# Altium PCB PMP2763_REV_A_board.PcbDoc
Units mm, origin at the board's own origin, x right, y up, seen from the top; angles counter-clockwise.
Board outline 41.91 x 33.66 mm, 2 copper layers (Top Layer, Top, Bottom Layer, Bottom); 43 components, 16 nets, 82 pads, 29 vias.
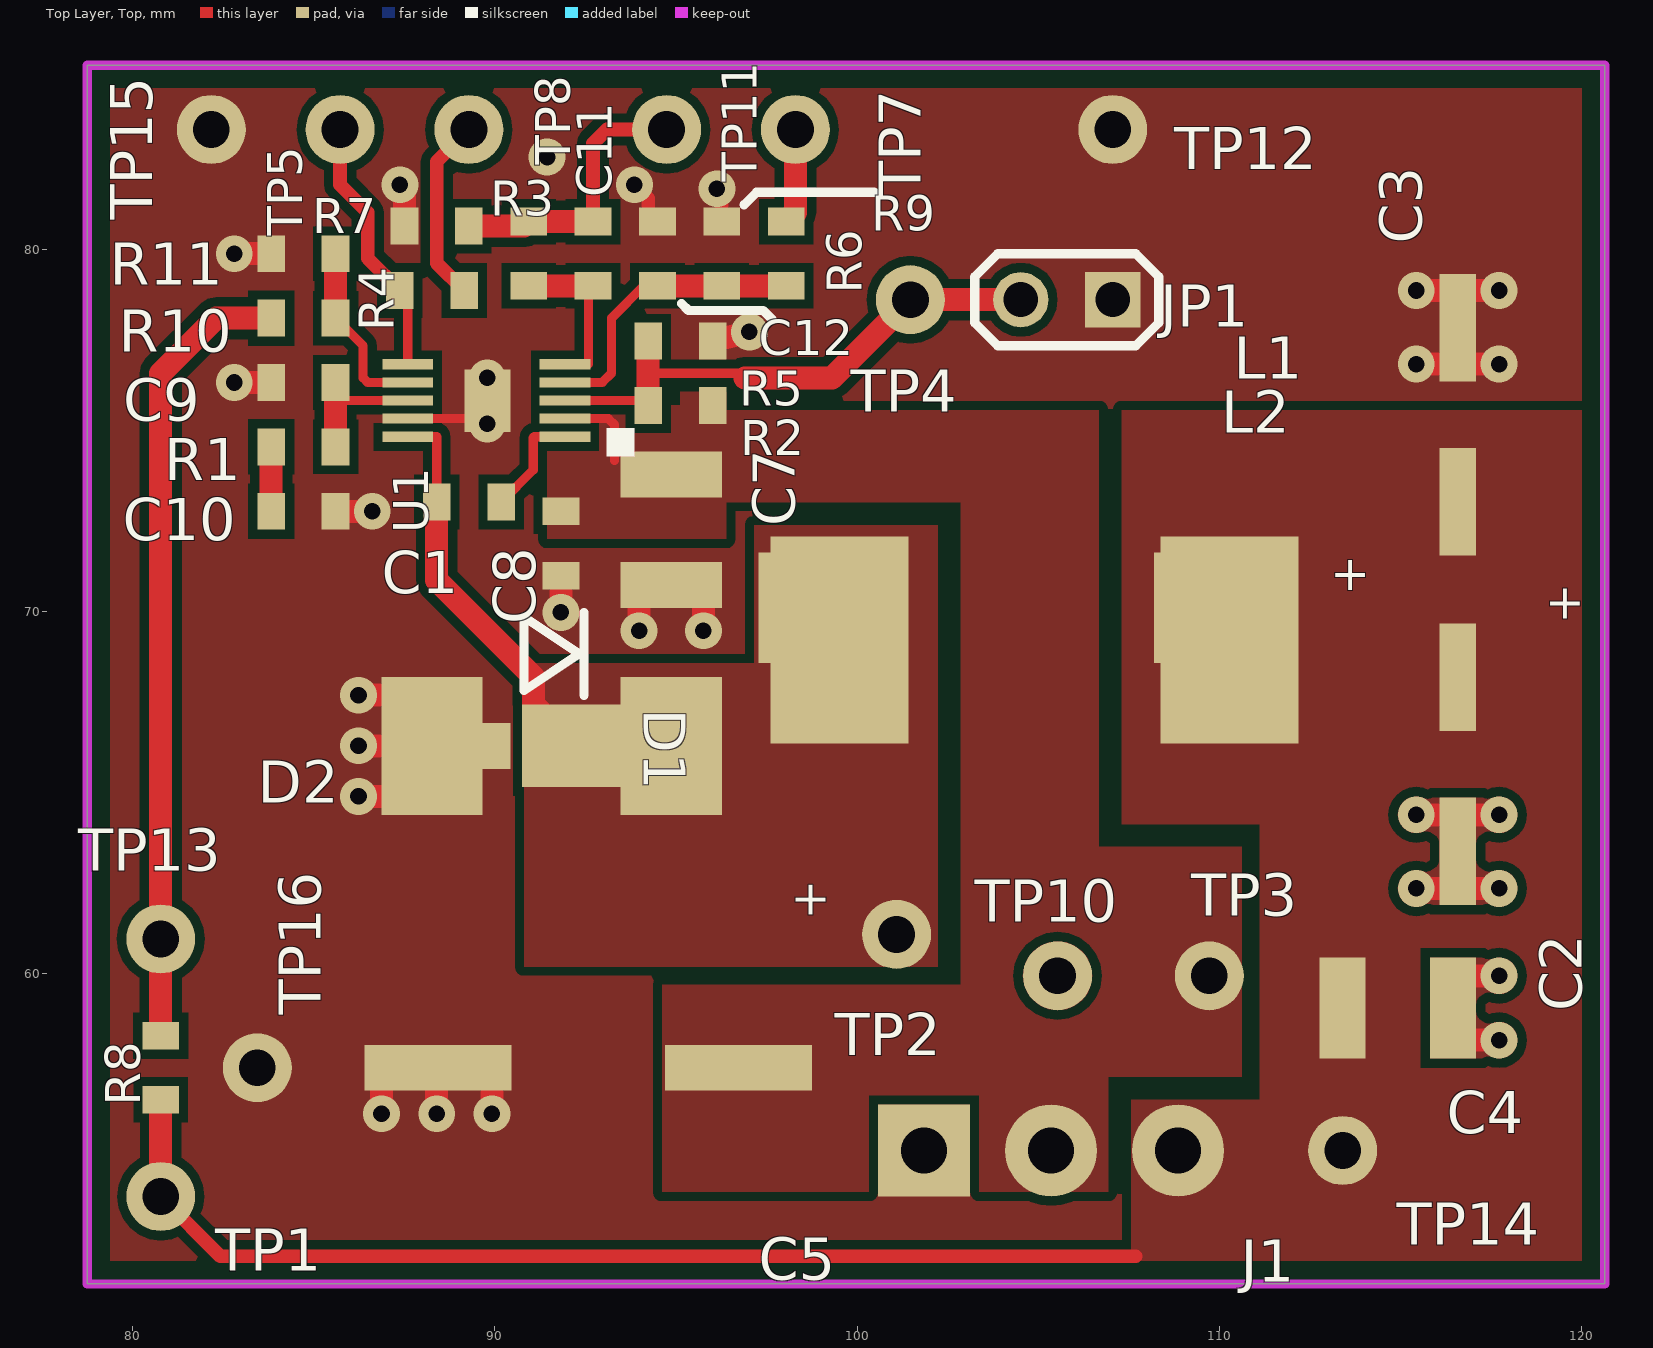
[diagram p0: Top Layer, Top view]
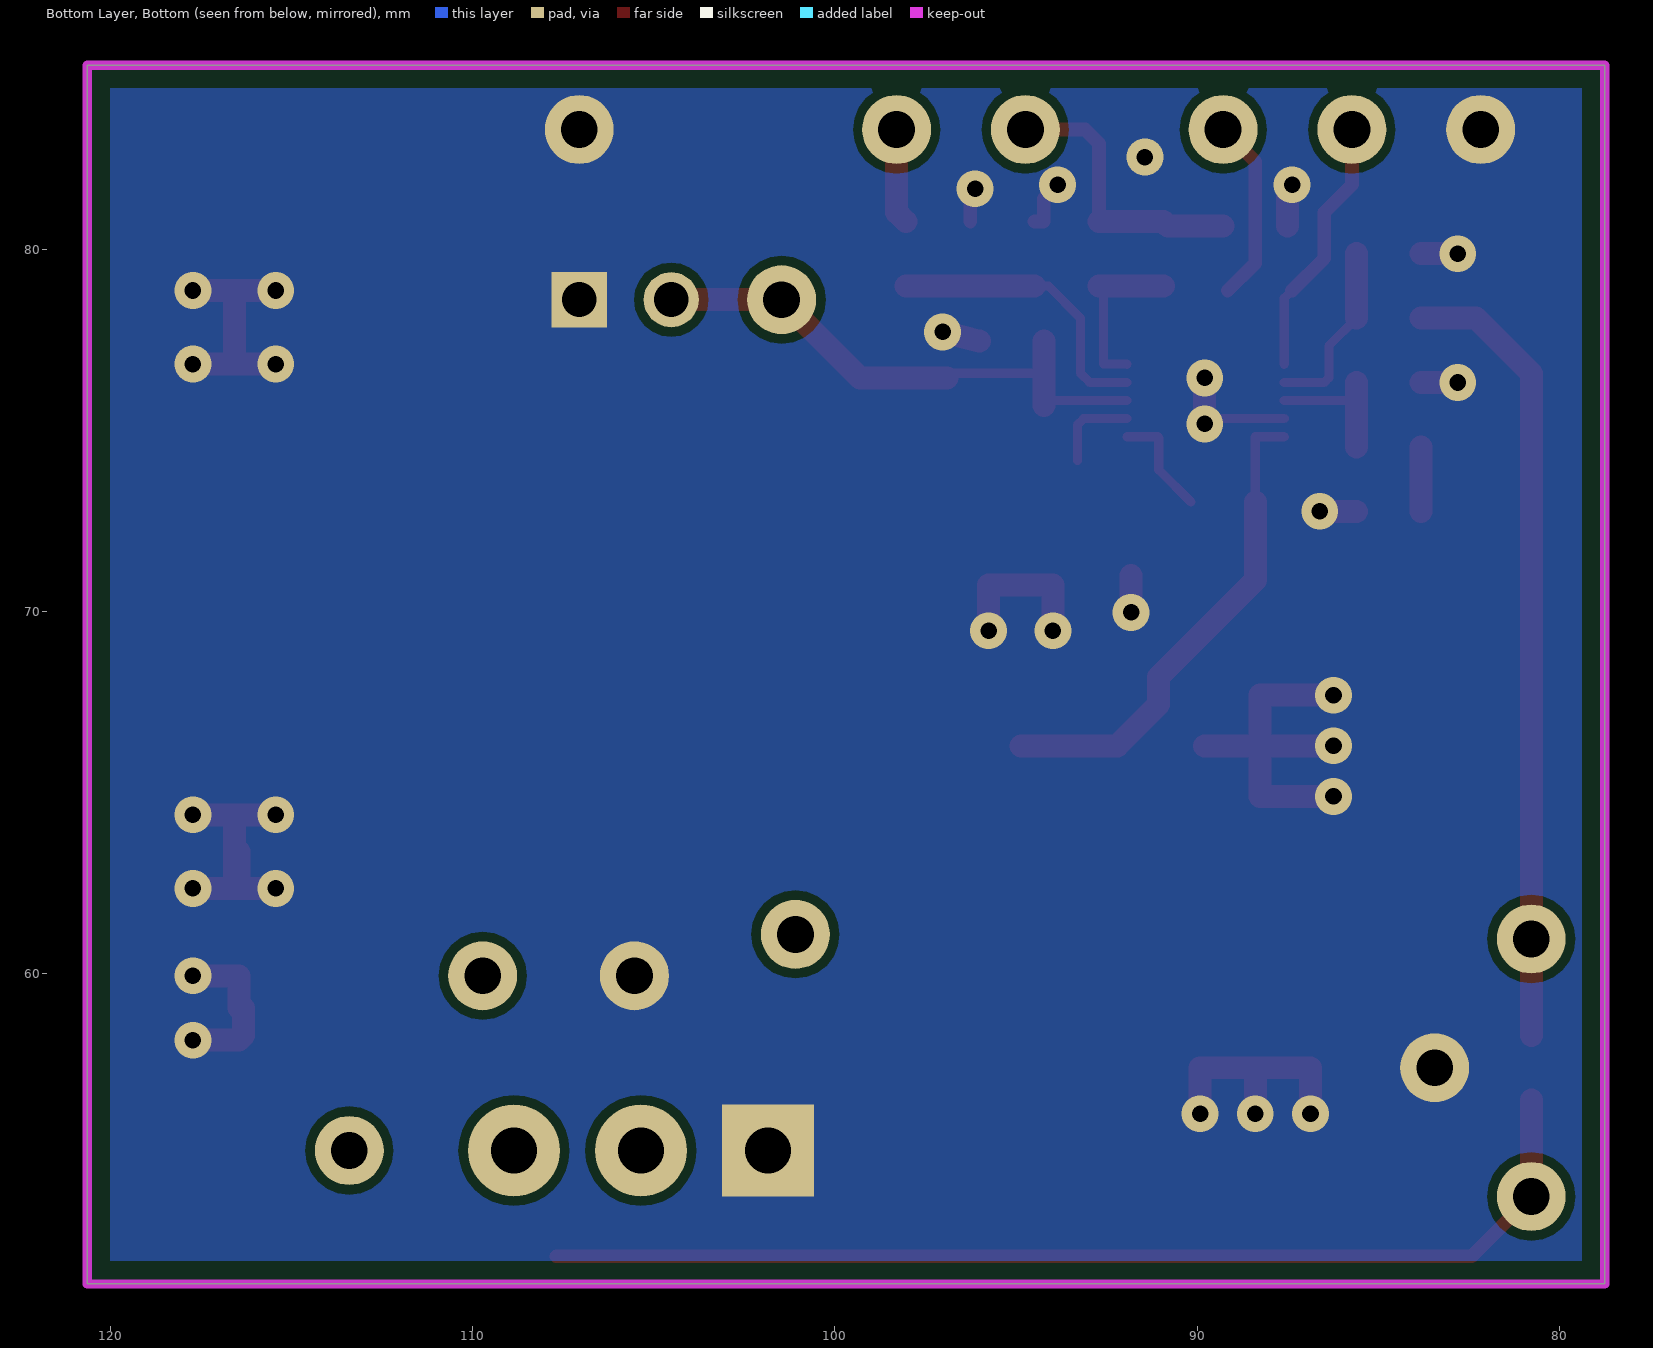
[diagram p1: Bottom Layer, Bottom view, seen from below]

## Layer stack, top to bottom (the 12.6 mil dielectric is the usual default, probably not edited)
Top Solder, Top Mask: solder mask 0.0102, Solder Resist, Dk 3.5
Top Layer, Top: signal copper 0.0356
Dielectric 1: dielectric 0.32, FR-4, Dk 4.8
Bottom Layer, Bottom: signal copper 0.0356
Bottom Solder, Bot Mask: solder mask 0.0102, Solder Resist, Dk 3.5

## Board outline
78.74,51.435 78.74,85.09 120.65,85.09 120.65,51.435

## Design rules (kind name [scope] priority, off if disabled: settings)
Clearance [All] p1: gap=0.254 ignorepadtopadclearanceinfootprint=FALSE except(0: Arc-Hole Track-Hole SMDPad-Hole THPad-Hole Via-Hole Fill-Hole Poly-Hole Region-Hole Text-Hole; 0.218: THPad-THPad; 0.231: Arc-THPad Track-THPad; 0.244: Arc-Arc Arc-Track Track-Track)
ComponentClearance [All] p1 off: gap=0.254 collisioncheckmode=3 verticalgap=0.254 showdistances=FALSE
HoleSize [All] p1: absolutevalues=TRUE maxlimit=2.54 minlimit=0.3 maxpercent=80.000 minpercent=20.000
PlaneClearance [All] p1: clearance=0.254
PolygonConnect PolygonConnect_10 [IsPolygon And InNet('GND') And OnLayer('Bottom Layer, Bottom') vs IsVia] p1: connectstyle=Direct reliefconductorwidth=0.381 reliefentries=4 polygonreliefangle="90 Angle" airgapwidth=0.254
PolygonConnect PolygonConnect_9 [IsPolygon And InNet('GND') And OnLayer('Bottom Layer, Bottom') vs IsPad] p2: connectstyle=Direct reliefconductorwidth=0.381 reliefentries=4 polygonreliefangle="90 Angle" airgapwidth=0.254
PolygonConnect PolygonConnect_8 [IsPolygon And InNet('GND') And OnLayer('Top Layer, Top') vs IsVia] p3: connectstyle=Direct reliefconductorwidth=0.381 reliefentries=4 polygonreliefangle="90 Angle" airgapwidth=0.254
PolygonConnect PolygonConnect_7 [IsPolygon And InNet('GND') And OnLayer('Top Layer, Top') vs IsPad] p4: connectstyle=Direct reliefconductorwidth=0.381 reliefentries=4 polygonreliefangle="90 Angle" airgapwidth=0.254
PolygonConnect PolygonConnect_6 [IsPolygon And InNet('PH') And OnLayer('Top Layer, Top') vs IsVia] p5: connectstyle=Direct reliefconductorwidth=0.381 reliefentries=4 polygonreliefangle="90 Angle" airgapwidth=0.254
PolygonConnect PolygonConnect_5 [IsPolygon And InNet('PH') And OnLayer('Top Layer, Top') vs IsPad] p6: connectstyle=Direct reliefconductorwidth=0.381 reliefentries=4 polygonreliefangle="90 Angle" airgapwidth=0.254
PolygonConnect PolygonConnect_4 [IsPolygon And InNet('VIN') And OnLayer('Top Layer, Top') vs IsVia] p7: connectstyle=Direct reliefconductorwidth=0.381 reliefentries=4 polygonreliefangle="90 Angle" airgapwidth=0.254
PolygonConnect PolygonConnect_3 [IsPolygon And InNet('VIN') And OnLayer('Top Layer, Top') vs IsPad] p8: connectstyle=Direct reliefconductorwidth=0.381 reliefentries=4 polygonreliefangle="90 Angle" airgapwidth=0.254
PolygonConnect PolygonConnect_2 [IsPolygon And InNet('VOUT') And OnLayer('Top Layer, Top') vs IsVia] p9: connectstyle=Direct reliefconductorwidth=0.381 reliefentries=4 polygonreliefangle="90 Angle" airgapwidth=0.254
PolygonConnect PolygonConnect_1 [IsPolygon And InNet('VOUT') And OnLayer('Top Layer, Top') vs IsPad] p10: connectstyle=Direct reliefconductorwidth=0.381 reliefentries=4 polygonreliefangle="90 Angle" airgapwidth=0.254
PolygonConnect [All] p11: connectstyle=Relief reliefconductorwidth=0.254 reliefentries=4 polygonreliefangle="90 Angle" airgapwidth=0.254
RoutingVias [All] p1: holewidth=0.711 width=1.27 viastyle="Through Hole" minholewidth=0.3 minwidth=0.7 maxholewidth=1 maxwidth=2
SolderMaskExpansion [All] p1: expansion=0.102 istentingtop=FALSE
Width [All] p1: maxlimit=2 minlimit=0.2 preferedwidth=0.8 toplayer_prefwidth=0.5 minimp=50.000000 maximp=50.000000 favimp=50.000000
27 further rules are at their usual default settings.

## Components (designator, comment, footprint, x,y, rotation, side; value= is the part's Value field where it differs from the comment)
C1 "Open" C603 89.281,73.025 r0 top
C2 "220uF" CAP_ALUM_FK-D 116.586,65.786 r0 top
C3 "Open" CAP_ALUM_FK-D 116.586,75.438 r180 top
C4 "10uF" C1210 114.935,59.055 r180 top
C5 "220uF" CAP_ALUM_FK-G 92.583,57.404 r270 top
C7 "Open" C1210 94.869,72.263 r90 top
C8 "0.1uF" C603 91.821,71.882 r90 top (schematic designator C9)
C9 "Open" C603 84.709,76.327 r0 top
C10 "Open" C603 84.709,72.771 r180 top
C11 "Open" C603 92.71,79.883 r270 top
C12 "Open" C603 94.488,79.883 r270 top
D1 "Open" D_457-04 92.329,66.294 r270 top
D2 "MBRS340" MOT_SMC_CASE 91.567,66.294 r180 top
J1 "ED555/3DS" TB_3X3.5MM 101.854,55.118 r0 top
JP1 "PTC36SAAN" HDR100_1X2 107.061,78.613 r180 top
L1 "Open" IND_DO3316P 104.14,70.104 r180 top
L2 "15 uH" IND_DR127 104.902,69.215 r90 top
R1 "open" R603 84.709,74.549 r180 top
R2 "open" R603 95.123,75.692 r0 top
R3 "open" R603 90.932,79.883 r270 top
R4 "open" R603 88.265,78.867 r180 top (schematic designator R5)
R5 "open" R603 95.123,77.47 r180 top
R6 "open" R603 98.044,79.883 r90 top
R7 "open" R603 88.392,80.645 r0 top
R8 "open" R603 80.772,57.404 r270 top
R9 "open" R603 96.266,79.883 r270 top
R10 "open" R603 84.709,78.105 r180 top
R11 "open" R603 84.709,79.883 r0 top
TP1 "5000" TH-40 80.772,53.848 r0 top
TP2 "5000" TH-40 101.092,61.087 r0 top
TP3 "5000" TH-40 109.728,59.944 r0 top
TP4 "5001" TH-40 101.473,78.613 r0 top
TP5 "5001" TH-40 85.725,83.312 r0 top
TP7 "5001" TH-40 98.298,83.312 r0 top
TP8 "5001" TH-40 89.281,83.312 r0 top
TP10 "5001" TH-40 105.537,59.944 r0 top
TP11 "5001" TH-40 94.742,83.312 r0 top
TP12 "5001" TH-40 107.061,83.312 r0 top
TP13 "5000" TH-40 80.772,60.96 r0 top
TP14 "5000" TH-40 113.411,55.118 r0 top
TP15 "5001" TH-40 82.169,83.312 r0 top
TP16 "5001" TH-40 83.439,57.404 r0 top
U1 "TPS54160DGQ" DGQ_10PWP 89.789,75.819 r180 top

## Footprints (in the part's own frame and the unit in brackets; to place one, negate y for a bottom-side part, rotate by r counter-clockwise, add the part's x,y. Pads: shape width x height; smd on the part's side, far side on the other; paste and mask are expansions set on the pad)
C603 [mil]
  rect 30x40 smd: 1(-35,0) 2(35,0)
C1210 [mil]
  rect 50x110 smd: 1(-60,0) 2(60,0)
CAP_ALUM_FK-D [mil]
  rect 40x117 smd: 1(0,94.5) 2(0,-94.5)
CAP_ALUM_FK-G [mil]
  rect 50x160 smd: 1(0,163.3) 2(0,-163.7)
D_457-04 [mil]
  rect 90x115 smd: 1(0,-5)
  rect 50x50 smd: 2(0,-100)
DGQ_10PWP [mil]
  rect 55x11 smd: 1(-84.5,39) 2(-84.5,19.3) 3(-84.5,-0.4) 4(-84.5,-20.1) 5(-84.5,-39.8) 6(86.5,-39.8) 7(86.5,-20.1) 8(86.5,-0.4) 9(86.5,19.3) 10(86.5,39)
  rect 50x68 smd: 11(0,0)
  silkscreen extent -160,30 -130,60
HDR100_1X2 [mil]
  rect 60x60 hole 38: 1(0,0)
  round 60 hole 38: 2(100,0)
  silkscreen extent -50,-50 150,50
IND_DO3316P [mil]
  rect 120x120 smd: 1(210,0) 2(-220,0)
IND_DR127 [mil]
  rect 225x150 smd: 1(0,212) 2(0,-212)
MOT_SMC_CASE [mil]
  rect 110x150 smd: 1(-130,0) 2(130,0)
  silkscreen extent -35,-145 30,-55
R603 [mil]
  rect 30x40 smd: 1(-35,0) 2(35,0)
TB_3X3.5MM [mil]
  rect 100x100 hole 50: 1(0,0)
  round 100 hole 50: 2(138,0) 3(276,0)
TH-40 [mil]
  round 75 hole 40: 1(0,0)

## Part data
C1 C12: library part GRM188R71E104KA01D, "CAP, CERM, 0.1 µF, 25 V, +/- 10%, X7R, 0603"
C2 C3 C4 C5 C7: library part GRM31CR72A225KA73L, "CAP, CERM, 2.2 µF, 100 V,+/- 10%, X7R, 1206"
C8: library part GRM1885C1H470JA01D, "CAP, CERM, 47 pF, 50 V,+/- 5%, C0G/NP0, 0603"
C9 C11: "Capacitor, Ceramic, vvV, [temp],  [tol]"
C10: library part GRM188R71E472KA01D, "CAP, CERM, 4700 pF, 25 V,+/- 10%, X7R, 0603"
D1: "Diode, Schottky, 1A, 40V"
D2: library part PMEG6020ER,115, "Diode, Schottky, 60 V, 2 A, SOD-123W"
J1: "Terminal Block, 6A, 3.5mm Pitch, 3-Pos, TH"
JP1: "Header, 2-pin,  100mil spacing, (36-pin strip)"
L1: "Inductor, SMT, yyA, zzmilliohm"
L2: library part CMP-0085398-2, "Inductor, Shielded, Composite, 33 µH, 3.6 A, 0.105 ohm, AEC-Q200 Grade 1, SMD"
R1: library part CRCW0603100KFKEA, "RES, 100 k, 1%, 0.1 W, 0603"
R2: library part CRCW0603130KFKEA, "RES, 130 k, 1%, 0.1 W, 0603"
R3: library part CRCW0603412KFKEA, "RES, 412 k, 1%, 0.1 W, 0603"
R4: library part CRCW060349K9FKEA, "RES, 49.9 k, 1%, 0.1 W, 0603"
R5 R6 R7 R9: "Resistor, Chip, 1/16W, 1%"
R8: library part CRCW060349R9FKEA, "RES, 49.9, 1%, 0.1 W, 0603"
R10: library part CRCW0603182KFKEA, "RES, 182 k, 1%, 0.1 W, 0603"
R11: library part CRCW06033K32FKEA, "RES, 3.32 k, 1%, 0.1 W, 0603"
TP1 TP3: "Test Point, Miniature, Red, TH"
TP2 TP4: library part 5002, "Test Point, Miniature, White, TH"
TP5 TP7 TP8 TP10 TP11 TP15: "Test Point,  Black, Thru Hole Color Keyed"
TP12: library part 5117, "Test Point, Miniature, Blue, TH"
TP13: library part 5004, "Test Point, Miniature, Yellow, TH"
TP14: library part 5001, "Test Point, Miniature, Black, TH"
TP16: "Test Point, Miniature, Black, TH"
U1: library part TPS54040ADGQ, "1.5 A, 60 V Step Down DC/DC Converter with Eco-mode, DGQ0010D"

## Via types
v1: diameter 1.016, hole 0.457, Top Layer, Top to Bottom Layer, Bottom, 29 vias

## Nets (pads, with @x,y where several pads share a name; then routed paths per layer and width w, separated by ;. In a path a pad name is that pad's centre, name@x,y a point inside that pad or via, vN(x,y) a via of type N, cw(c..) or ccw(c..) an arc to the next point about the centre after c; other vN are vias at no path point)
EN: JP1.2 R2.1 R5.2 TP4.1 U1.3 | length 16.3
  Top Layer, Top w0.254: U1.3 94.097,75.829 R2.1 ; R5.2 94.234,76.581 96.901,76.581 96.901,76.454
  Top Layer, Top w0.635: R2.1 94.234,76.581 R5.2 ; 96.901,76.454 99.314,76.454 TP4.1 JP1.2
GND: C2.2 C3.2 C4.1 C5.2 C7.1 C8.1 C9.1 C10.1 C12.1 D1.2 D2.2 J1.1 JP1.1 R5.1 R7.1 R9.1 R11.1 TP10.1 TP12.1 TP15.1 TP16.1 U1.9 U1.11 | length 54.9
  Top Layer, Top w0.254: U1.9 87.594,75.331 89.789,75.331 v1(89.789,75.184)
  Top Layer, Top w0.381: v1(93.853,81.788) 94.234,81.407 94.234,80.772 C12.1 ; v1(96.131,81.679) 96.266,81.661 R9.1
  Top Layer, Top w0.635: v1(82.804,76.327) C9.1 ; v1(82.804,79.883) R11.1 ; C10.1 v1(86.614,72.771) ; v1(86.233,64.897) 88.265,64.897 D2.2 ; v1(86.233,66.294) D2.2 ; v1(86.233,67.691) 88.265,67.691 D2.2 ; v1(86.868,56.134) 86.868,57.404 C5.2@88.392,57.404 ; v1(87.376,81.788) 87.503,81.661 R7.1 ; v1(88.392,56.134) C5.2@88.392,57.404 ; D1.2 D2.2 ; v1(89.789,75.184) 89.789,75.331 U1.11 v1(89.789,76.454) ; v1(89.916,56.134) 89.916,57.404 C5.2 C5.2@88.392,57.404 ; v1(91.821,69.977) C8.1 ; v1(93.98,69.469) 93.98,70.739 C7.1 95.758,70.739 v1(95.758,69.469) ; R5.1 v1(97.028,77.724) ; v1(115.443,62.357) C2.2@116.586,62.357 ; v1(115.443,64.389) C2.2@116.586,64.389 ; v1(115.443,76.835) C3.2@116.586,76.835 ; v1(115.443,78.867) C3.2@116.586,78.867 ; v1(117.729,58.166) 116.459,58.166 116.332,58.293 116.332,59.055 C4.1 116.459,59.944 v1(117.729,59.944) ; v1(117.729,62.357) C2.2@116.586,62.357 ; v1(117.729,64.389) C2.2@116.586,64.389 ; v1(117.729,76.835) C3.2@116.586,76.835 ; v1(117.729,78.867) C3.2@116.586,78.867 ; C2.2@116.586,62.357 C2.2 ; C2.2@116.586,62.357 116.459,62.484 116.459,63.373 C2.2 ; C2.2 C2.2@116.586,64.389 ; C2.2 C2.2@116.586,64.389 ; C3.2@116.586,76.835 C3.2 ; C3.2@116.586,76.835 C3.2 ; C3.2 C3.2@116.586,78.867
  other v1: 91.44,82.55
NET00006: C1.2 U1.1 | length 3
  Top Layer, Top w0.254: C1.2 91.059,73.914 91.059,74.803 91.084,74.828 U1.1
NET00007: R4.2 TP5.1 U1.6 | length 7.3
  Top Layer, Top w0.254: R4.2 87.592,78.651 U1.6
  Top Layer, Top w0.381: TP5.1 85.725,81.788 86.487,81.026 86.487,79.756 R4.2
NET00010: R10.1 R11.2 U1.7 | length 5
  Top Layer, Top w0.254: R10.1 86.36,77.343 86.36,76.454 86.487,76.327 87.503,76.327 U1.7
  Top Layer, Top w0.635: R10.1 R11.2
NET00012: R4.1 TP8.1 | length 5.1
  Top Layer, Top w0.381: R4.1 88.392,79.629 88.392,82.423 TP8.1
NET00015: R8.1 R10.2 TP13.1 | length 22
  Top Layer, Top w0.635: R8.1 TP13.1 80.772,76.581 82.296,78.105 R10.2
NET00019: C11.2 R3.2 U1.5 | length 4.6
  Top Layer, Top w0.254: U1.5 91.948,76.835 92.583,76.835 92.583,78.867 C11.2
  Top Layer, Top w0.635: R3.2 C11.2
NET00020: C11.1 R3.1 R7.2 TP11.1 | length 7.8
  Top Layer, Top w0.381: C11.1 92.71,82.931 93.091,83.312 TP11.1
  Top Layer, Top w0.635: R7.2 90.805,80.645 R3.1 C11.1
NET00023: C10.2 R1.2 | length 1.8
  Top Layer, Top w0.635: C10.2 R1.2
NET00024: C9.2 R1.1 U1.8 | length 4.3
  Top Layer, Top w0.254: C9.2 85.598,75.829 U1.8
  Top Layer, Top w0.635: R1.1 85.598,75.829 C9.2
NET00026: C12.2 R6.1 R9.2 U1.4 | length 8.1
  Top Layer, Top w0.254: U1.4 92.967,76.33 93.218,76.581 93.218,78.105 94.107,78.994 C12.2
  Top Layer, Top w0.635: C12.2 R9.2 R6.1
NET00029: R6.2 TP7.1 | length 2.6
  Top Layer, Top w0.635: R6.2 98.298,81.026 TP7.1
PH: C1.1 D1.1 D2.1 L1.1 L2.1 TP2.1 U1.10 | length 13.6
  Top Layer, Top w0.254: U1.10 87.594,74.831 88.395,74.831 88.395,73.028 C1.1
  Top Layer, Top w0.635: C1.1 88.392,70.866 91.059,68.199 91.059,67.437 D1.1 D2.1
VIN: C5.1 C7.2 C8.2 J1.2 R2.2 TP3.1 U1.2 | length 2.4
  Top Layer, Top w0.254: U1.2 93.134,75.329 93.302,75.161 93.302,74.173
VOUT: C2.1 C3.1 C4.2 J1.3 L1.2 L2.2 R8.2 TP1.1 TP14.1 | length 30.3
  Top Layer, Top w0.381: TP1.1 82.423,52.197 107.696,52.197
  Top Layer, Top w0.635: TP1.1 R8.2

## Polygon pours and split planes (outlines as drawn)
VOUT on Top Layer, Top "Top Layer, Top-VOUT" (solid, pour order 2): 107.315,64.135 111.125,64.135 111.125,56.515 107.569,56.515 107.569,52.07 120.015,52.07 120.015,75.565 107.315,75.565
VIN on Top Layer, Top "Top Layer, Top-VIN" (solid, pour order 4): 91.44,72.009 96.393,72.009 96.393,76.073 95.123,76.073 95.123,75.692 93.345,75.692 91.44,75.692 91.44,73.406
PH on Top Layer, Top "Top Layer, Top-PH" (solid, pour order 6): 90.805,60.198 96.647,60.198 97.409,60.198 102.235,60.198 102.235,68.58 102.235,72.39 97.155,72.39 97.155,68.58 96.52,68.58 90.805,68.58
VIN on Top Layer, Top "Top Layer, Top-VIN 1" (solid, pour order 8): 94.615,53.975 106.934,53.975 106.934,57.15 110.617,57.15 110.617,63.5 106.68,63.5 106.68,75.565 95.885,75.565 95.885,73.025 102.87,73.025 102.87,59.69 94.615,59.69
GND on Top Layer, Top "Top Layer, Top-GND" (solid, pour order 10): 79.375,52.07 120.015,52.07 120.015,84.455 79.375,84.455
GND on Bottom Layer, Bottom "Bottom Layer, Bottom-GND" (solid, pour order 12): 120.015,52.07 120.015,84.455 79.375,84.455 79.375,52.07

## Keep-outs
Keep-Out Layer, Board:
  the board outline again, w0.254
  text "PMP2763 REV A" at 78.74,46.355 h1.59

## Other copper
Top Layer, Top:
  text "LAYER 1-TOP" at 99.06,46.355 h1.59
Bottom Layer, Bottom:
  text "LAYER 2-BOTTOM" at 121.285,46.355 h1.59

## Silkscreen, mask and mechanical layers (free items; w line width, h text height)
Top Overlay, Top Silk:
  lines w0.254: 95.148,78.511 95.344,78.316 97.406,78.316 97.668,78.054 ; 96.881,81.237 97.226,81.582 100.477,81.582
  text "SILK-LAYER 1" at 99.06,46.355 h1.59
Bottom Overlay, Bot Silk:
  text "SILK-LAYER 2" at 121.285,46.355 h1.59
Top Solder, Top Mask:
  text "MASK-LAYER 1" at 99.06,46.355 h1.59
Bottom Solder, Bot Mask:
  text "PMP2763 REV A" at 111.125,65.405 h1.59
  text "2007" at 119.38,52.705 h0.95
  text "MASK-LAYER 2" at 121.285,46.355 h1.59
Mechanical 3, FABRICATION:
  text "FABRICATION" at 78.74,42.545 h1.59

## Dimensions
120.65,85.09 to 78.74,51.435 on Mechanical 3, FABRICATION
78.74,51.435 to 120.65,85.09 on Mechanical 3, FABRICATION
